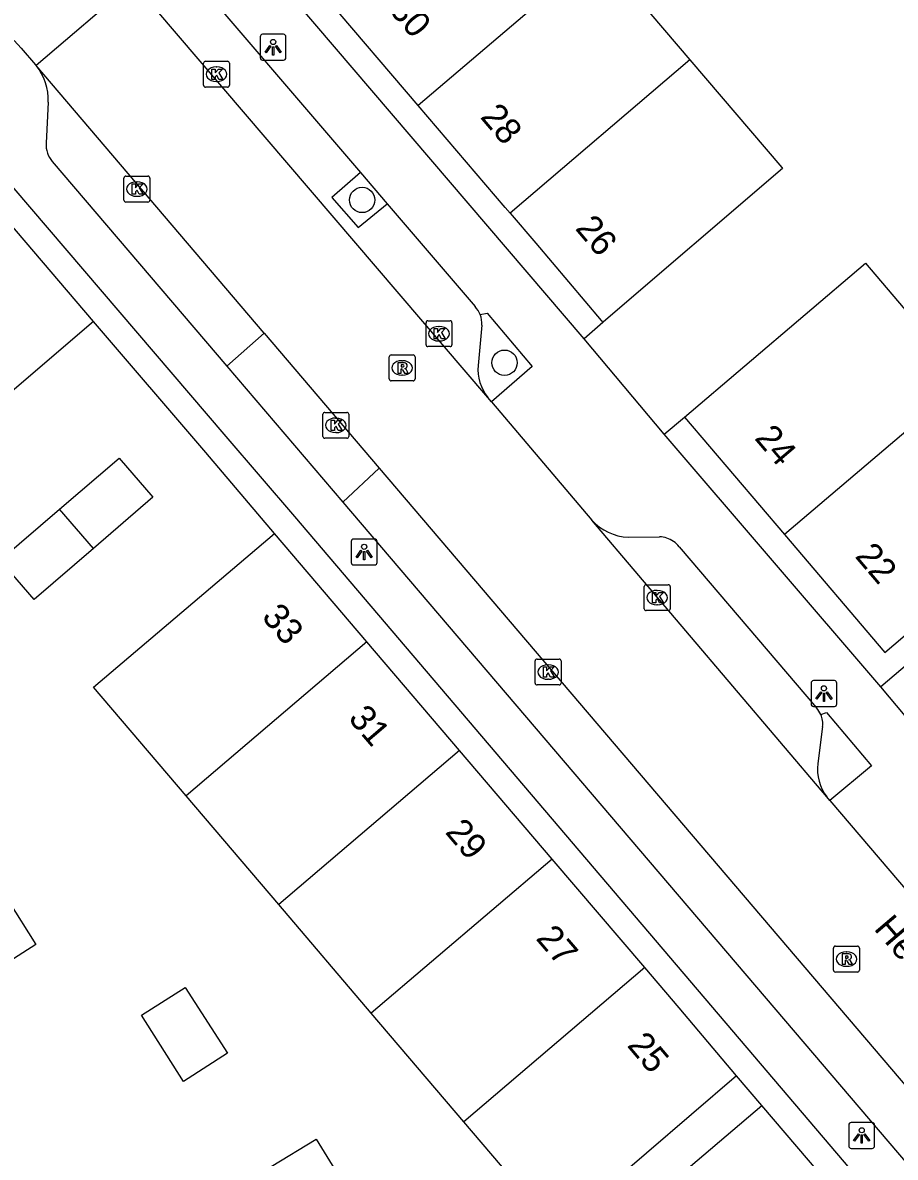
# Model space of a CAD drawing. Extents: x 160379 to 161131, y 383940 to 384849.
# Drawn here: x 160537.01 to 160570.71, y 384580.77 to 384624.58 of the extents above; entities that cross this region are included whole.
import ezdxf

# ---------------------------------------------------------------- set-up
doc = ezdxf.new("R2010")
doc.units = 0
for name, color, linetype in [('IMGEO_Boom', 7, 'Continuous'), ('IMGEO_Erf', 7, 'Continuous'), ('IMGEO_Groenvoorziening', 7, 'Continuous'), ('IMGEO_Kolk', 7, 'Continuous'), ('IMGEO_Lichtpunt', 7, 'Continuous'), ('IMGEO_Openbare_ruimte_label', 7, 'Continuous'), ('IMGEO_Pand', 7, 'Continuous'), ('IMGEO_Pand_nummerreeks', 7, 'Continuous'), ('IMGEO_Parkeervlak_open', 7, 'Continuous'), ('IMGEO_Rijbaan_lokaal_open', 7, 'Continuous'), ('IMGEO_Rioolput', 7, 'Continuous'), ('IMGEO_Voetpad_open', 7, 'Continuous')]:
    doc.layers.add(name, color=color, linetype=linetype)

msp = doc.modelspace()

# ---------------------------------------------------------------- linework, layer by layer
at = {"layer": 'IMGEO_Boom'}
for centre in [(160550.12, 384617.738), (160555.619, 384611.454)]:
    msp.add_circle(centre, 0.489, dxfattribs=at)
at = {"layer": 'IMGEO_Erf'}
for points in [[(160546.73, 384604.858), (160544.085, 384607.99), (160539.738, 384613.041)], [(160559.422, 384613.011), (160558.691, 384612.377)], [(160561.787, 384608.701), (160562.572, 384609.354)], [(160565.562, 384582.774), (160564.577, 384583.923)]]:
    msp.add_lwpolyline(points, dxfattribs=at)
at = {"layer": 'IMGEO_Groenvoorziening'}
msp.add_lwpolyline([(160578.569, 384607.304), (160579.15, 384606.609), (160578.387, 384605.942), (160570.15, 384598.933)], dxfattribs=at)
at = {"layer": 'IMGEO_Kolk'}
for p, q in [((160543.994, 384622.168), (160543.994, 384623.02)), ((160544.069, 384623.094), (160544.921, 384623.094)), ((160544.482, 384622.874), (160544.507, 384622.874)), ((160544.995, 384623.02), (160544.995, 384622.168)), ((160544.921, 384622.094), (160544.069, 384622.094)), ((160544.505, 384622.314), (160544.48, 384622.314)), ((160540.921, 384617.733), (160540.921, 384618.585)), ((160540.996, 384618.659), (160541.848, 384618.659)), ((160541.922, 384618.585), (160541.922, 384617.733)), ((160541.409, 384618.439), (160541.434, 384618.439)), ((160541.848, 384617.659), (160540.996, 384617.659)), ((160541.432, 384617.879), (160541.407, 384617.879)), ((160552.587, 384612.149), (160552.587, 384613.001)), ((160552.662, 384613.075), (160553.514, 384613.075)), ((160553.075, 384612.855), (160553.1, 384612.855)), ((160553.588, 384613.001), (160553.588, 384612.149)), ((160553.514, 384612.075), (160552.662, 384612.075)), ((160553.098, 384612.295), (160553.073, 384612.295)), ((160548.604, 384608.611), (160548.604, 384609.463)), ((160548.679, 384609.537), (160549.531, 384609.537)), ((160549.092, 384609.317), (160549.117, 384609.317)), ((160549.605, 384609.463), (160549.605, 384608.611)), ((160549.531, 384608.537), (160548.679, 384608.537)), ((160549.115, 384608.757), (160549.09, 384608.757)), ((160561.017, 384601.957), (160561.017, 384602.809)), ((160561.092, 384602.883), (160561.944, 384602.883)), ((160562.018, 384602.809), (160562.018, 384601.957)), ((160561.505, 384602.663), (160561.53, 384602.663)), ((160561.944, 384601.883), (160561.092, 384601.883)), ((160561.528, 384602.103), (160561.503, 384602.103)), ((160556.802, 384599.085), (160556.802, 384599.937)), ((160556.877, 384600.011), (160557.729, 384600.011)), ((160557.29, 384599.791), (160557.315, 384599.791)), ((160557.803, 384599.937), (160557.803, 384599.085)), ((160557.313, 384599.231), (160557.288, 384599.231)), ((160557.729, 384599.011), (160556.877, 384599.011))]:
    msp.add_line(p, q, dxfattribs=at)
for points in [[(160543.994, 384622.168), (160543.994, 384623.02)], [(160544.069, 384623.094), (160544.921, 384623.094)], [(160544.995, 384623.02), (160544.995, 384622.168)], [(160544.315, 384622.794), (160544.438, 384622.794), (160544.438, 384622.643), (160544.568, 384622.794), (160544.732, 384622.794), (160544.586, 384622.643), (160544.739, 384622.394), (160544.587, 384622.394), (160544.502, 384622.558), (160544.438, 384622.491), (160544.438, 384622.394), (160544.315, 384622.394), (160544.315, 384622.794)], [(160544.921, 384622.094), (160544.069, 384622.094)], [(160540.921, 384617.733), (160540.921, 384618.585)], [(160540.996, 384618.659), (160541.848, 384618.659)], [(160541.922, 384618.585), (160541.922, 384617.733)], [(160541.242, 384618.359), (160541.365, 384618.359), (160541.365, 384618.208), (160541.495, 384618.359), (160541.659, 384618.359), (160541.513, 384618.208), (160541.666, 384617.959), (160541.514, 384617.959), (160541.429, 384618.123), (160541.365, 384618.056), (160541.365, 384617.959), (160541.242, 384617.959), (160541.242, 384618.359)], [(160541.848, 384617.659), (160540.996, 384617.659)], [(160552.587, 384612.149), (160552.587, 384613.001)], [(160552.662, 384613.075), (160553.514, 384613.075)], [(160552.908, 384612.775), (160553.031, 384612.775), (160553.031, 384612.624), (160553.161, 384612.775), (160553.325, 384612.775), (160553.179, 384612.624), (160553.332, 384612.375), (160553.18, 384612.375), (160553.095, 384612.539), (160553.031, 384612.472), (160553.031, 384612.375), (160552.908, 384612.375), (160552.908, 384612.775)], [(160553.588, 384613.001), (160553.588, 384612.149)], [(160553.514, 384612.075), (160552.662, 384612.075)], [(160548.604, 384608.611), (160548.604, 384609.463)], [(160548.679, 384609.537), (160549.531, 384609.537)], [(160549.605, 384609.463), (160549.605, 384608.611)], [(160548.925, 384609.237), (160549.048, 384609.237), (160549.048, 384609.086), (160549.178, 384609.237), (160549.342, 384609.237), (160549.196, 384609.086), (160549.349, 384608.837), (160549.197, 384608.837), (160549.112, 384609.001), (160549.048, 384608.934), (160549.048, 384608.837), (160548.925, 384608.837), (160548.925, 384609.237)], [(160549.531, 384608.537), (160548.679, 384608.537)], [(160561.017, 384601.957), (160561.017, 384602.809)], [(160561.092, 384602.883), (160561.944, 384602.883)], [(160562.018, 384602.809), (160562.018, 384601.957)], [(160561.338, 384602.583), (160561.461, 384602.583), (160561.461, 384602.432), (160561.591, 384602.583), (160561.755, 384602.583), (160561.609, 384602.432), (160561.762, 384602.183), (160561.61, 384602.183), (160561.525, 384602.347), (160561.461, 384602.28), (160561.461, 384602.183), (160561.338, 384602.183), (160561.338, 384602.583)], [(160561.944, 384601.883), (160561.092, 384601.883)], [(160556.802, 384599.085), (160556.802, 384599.937)], [(160556.877, 384600.011), (160557.729, 384600.011)], [(160557.123, 384599.711), (160557.246, 384599.711), (160557.246, 384599.56), (160557.376, 384599.711), (160557.54, 384599.711), (160557.394, 384599.56), (160557.547, 384599.311), (160557.395, 384599.311), (160557.31, 384599.475), (160557.246, 384599.408), (160557.246, 384599.311), (160557.123, 384599.311), (160557.123, 384599.711)], [(160557.803, 384599.937), (160557.803, 384599.085)], [(160557.729, 384599.011), (160556.877, 384599.011)]]:
    msp.add_lwpolyline(points, dxfattribs=at)
for centre, start, end in [((160544.071, 384623.018), 91.552, 178.448), ((160544.071, 384623.018), 91.552, 178.448), ((160544.919, 384623.018), 1.552, 88.448), ((160544.919, 384623.018), 1.552, 88.448), ((160544.071, 384622.17), 181.552, 268.448), ((160544.071, 384622.17), 181.552, 268.448), ((160544.919, 384622.17), 271.552, 358.448), ((160544.919, 384622.17), 271.552, 358.448), ((160540.998, 384618.583), 91.552, 178.448), ((160540.998, 384618.583), 91.552, 178.448), ((160541.846, 384618.583), 1.552, 88.448), ((160541.846, 384618.583), 1.552, 88.448), ((160540.998, 384617.735), 181.552, 268.448), ((160540.998, 384617.735), 181.552, 268.448), ((160541.846, 384617.735), 271.552, 358.448), ((160541.846, 384617.735), 271.552, 358.448), ((160552.664, 384612.999), 91.552, 178.448), ((160552.664, 384612.999), 91.552, 178.448), ((160553.512, 384612.999), 1.552, 88.448), ((160553.512, 384612.999), 1.552, 88.448), ((160552.664, 384612.151), 181.552, 268.448), ((160552.664, 384612.151), 181.552, 268.448), ((160553.512, 384612.151), 271.552, 358.448), ((160553.512, 384612.151), 271.552, 358.448), ((160548.681, 384609.461), 91.552, 178.448), ((160548.681, 384609.461), 91.552, 178.448), ((160549.529, 384609.461), 1.552, 88.448), ((160549.529, 384609.461), 1.552, 88.448), ((160548.681, 384608.613), 181.552, 268.448), ((160548.681, 384608.613), 181.552, 268.448), ((160549.529, 384608.613), 271.552, 358.448), ((160549.529, 384608.613), 271.552, 358.448), ((160561.094, 384602.807), 91.552, 178.448), ((160561.094, 384602.807), 91.552, 178.448), ((160561.942, 384602.807), 1.552, 88.448), ((160561.942, 384602.807), 1.552, 88.448), ((160561.094, 384601.959), 181.552, 268.448), ((160561.094, 384601.959), 181.552, 268.448), ((160561.942, 384601.959), 271.552, 358.448), ((160561.942, 384601.959), 271.552, 358.448), ((160556.879, 384599.935), 91.552, 178.448), ((160556.879, 384599.935), 91.552, 178.448), ((160557.727, 384599.935), 1.552, 88.448), ((160557.727, 384599.935), 1.552, 88.448), ((160556.879, 384599.087), 181.552, 268.448), ((160556.879, 384599.087), 181.552, 268.448), ((160557.727, 384599.087), 271.552, 358.448), ((160557.727, 384599.087), 271.552, 358.448)]:
    msp.add_arc(centre, 0.0765, start, end, dxfattribs=at)
for centre, major_axis, ratio, start_param, end_param in [((160544.481, 384622.594), (-0.387, 0.002), 0.722429, 4.712389, 7.853982), ((160544.506, 384622.594), (-0.39, 0.002), 0.717154, 1.570796, 4.712389), ((160541.408, 384618.159), (-0.387, 0.002), 0.722429, 4.712389, 7.853982), ((160541.433, 384618.159), (-0.39, 0.002), 0.717154, 1.570796, 4.712389), ((160553.074, 384612.575), (-0.387, 0.002), 0.722429, 4.712389, 7.853982), ((160553.099, 384612.575), (-0.39, 0.002), 0.717154, 1.570796, 4.712389), ((160549.091, 384609.037), (-0.387, 0.002), 0.722429, 4.712389, 7.853982), ((160549.116, 384609.037), (-0.39, 0.002), 0.717154, 1.570796, 4.712389), ((160561.504, 384602.383), (-0.387, 0.002), 0.722429, 4.712389, 7.853982), ((160561.529, 384602.383), (-0.39, 0.002), 0.717154, 1.570796, 4.712389), ((160557.289, 384599.511), (-0.387, 0.002), 0.722429, 4.712389, 7.853982), ((160557.314, 384599.511), (-0.39, 0.002), 0.717154, 1.570796, 4.712389)]:
    msp.add_ellipse(centre, major_axis=major_axis, ratio=ratio, start_param=start_param, end_param=end_param, dxfattribs=at)
at = {"layer": 'IMGEO_Lichtpunt'}
for p, q in [((160546.182, 384624.041), (160546.182, 384623.234)), ((160546.182, 384624.041), (160546.182, 384623.234)), ((160547.084, 384624.136), (160546.276, 384624.136)), ((160547.084, 384624.136), (160546.276, 384624.136)), ((160547.178, 384623.234), (160547.178, 384624.041)), ((160547.178, 384623.234), (160547.178, 384624.041)), ((160546.276, 384623.14), (160547.084, 384623.14)), ((160546.276, 384623.14), (160547.084, 384623.14)), ((160549.701, 384604.548), (160549.701, 384603.741)), ((160549.701, 384604.548), (160549.701, 384603.741)), ((160550.603, 384604.643), (160549.795, 384604.643)), ((160550.603, 384604.643), (160549.795, 384604.643)), ((160550.697, 384603.741), (160550.697, 384604.548)), ((160550.697, 384603.741), (160550.697, 384604.548)), ((160549.795, 384603.647), (160550.603, 384603.647)), ((160549.795, 384603.647), (160550.603, 384603.647)), ((160567.458, 384599.083), (160567.458, 384598.276)), ((160567.458, 384599.083), (160567.458, 384598.276)), ((160568.36, 384599.178), (160567.552, 384599.178)), ((160568.36, 384599.178), (160567.552, 384599.178)), ((160568.454, 384598.276), (160568.454, 384599.083)), ((160568.454, 384598.276), (160568.454, 384599.083)), ((160567.552, 384598.182), (160568.36, 384598.182)), ((160567.552, 384598.182), (160568.36, 384598.182)), ((160569.818, 384582.115), (160569.01, 384582.115)), ((160569.818, 384582.115), (160569.01, 384582.115)), ((160568.916, 384582.02), (160568.916, 384581.213)), ((160568.916, 384582.02), (160568.916, 384581.213)), ((160569.912, 384581.213), (160569.912, 384582.02)), ((160569.912, 384581.213), (160569.912, 384582.02)), ((160569.01, 384581.119), (160569.818, 384581.119)), ((160569.01, 384581.119), (160569.818, 384581.119))]:
    msp.add_line(p, q, dxfattribs=at)
for points in [[(160546.556, 384623.705), (160546.595, 384623.677), (160546.407, 384623.415), (160546.369, 384623.442), (160546.556, 384623.705)], [(160546.658, 384623.657), (160546.705, 384623.657), (160546.705, 384623.335), (160546.658, 384623.335), (160546.658, 384623.657)], [(160546.768, 384623.677), (160546.806, 384623.704), (160546.993, 384623.442), (160546.954, 384623.414), (160546.768, 384623.677)], [(160550.075, 384604.212), (160550.114, 384604.184), (160549.926, 384603.922), (160549.888, 384603.949), (160550.075, 384604.212)], [(160550.177, 384604.164), (160550.224, 384604.164), (160550.224, 384603.842), (160550.177, 384603.842), (160550.177, 384604.164)], [(160550.287, 384604.184), (160550.325, 384604.211), (160550.512, 384603.949), (160550.473, 384603.921), (160550.287, 384604.184)], [(160567.832, 384598.747), (160567.871, 384598.719), (160567.683, 384598.457), (160567.645, 384598.484), (160567.832, 384598.747)], [(160567.934, 384598.699), (160567.981, 384598.699), (160567.981, 384598.377), (160567.934, 384598.377), (160567.934, 384598.699)], [(160568.044, 384598.719), (160568.082, 384598.746), (160568.269, 384598.484), (160568.23, 384598.456), (160568.044, 384598.719)], [(160569.29, 384581.684), (160569.329, 384581.656), (160569.141, 384581.394), (160569.103, 384581.421), (160569.29, 384581.684)], [(160569.502, 384581.656), (160569.54, 384581.683), (160569.727, 384581.421), (160569.688, 384581.393), (160569.502, 384581.656)], [(160569.392, 384581.636), (160569.439, 384581.636), (160569.439, 384581.314), (160569.392, 384581.314), (160569.392, 384581.636)]]:
    msp.add_lwpolyline(points, dxfattribs=at)
for centre in [(160546.681, 384623.839), (160550.2, 384604.346), (160567.957, 384598.881), (160569.415, 384581.818)]:
    msp.add_circle(centre, 0.0994, dxfattribs=at)
for centre, start, end in [((160546.276, 384624.041), 90, 180), ((160546.276, 384624.041), 90, 180), ((160547.084, 384624.041), 0, 90), ((160547.084, 384624.041), 0, 90), ((160546.276, 384623.234), 180, 270), ((160546.276, 384623.234), 180, 270), ((160547.084, 384623.234), 270, 0), ((160547.084, 384623.234), 270, 360), ((160549.795, 384604.548), 90, 180), ((160549.795, 384604.548), 90, 180), ((160550.603, 384604.548), 0, 90), ((160550.603, 384604.548), 0, 90), ((160549.795, 384603.741), 180, 270), ((160549.795, 384603.741), 180, 270), ((160550.603, 384603.741), 270, 0), ((160550.603, 384603.741), 270, 360), ((160567.552, 384599.083), 90, 180), ((160567.552, 384599.083), 90, 180), ((160568.36, 384599.083), 0, 90), ((160568.36, 384599.083), 0, 90), ((160567.552, 384598.276), 180, 270), ((160567.552, 384598.276), 180, 270), ((160568.36, 384598.276), 270, 0), ((160568.36, 384598.276), 270, 360), ((160569.01, 384582.02), 90, 180), ((160569.01, 384582.02), 90, 180), ((160569.818, 384582.02), 0, 90), ((160569.818, 384582.02), 0, 90), ((160569.01, 384581.213), 180, 270), ((160569.01, 384581.213), 180, 270), ((160569.818, 384581.213), 270, 0), ((160569.818, 384581.213), 270, 360)]:
    msp.add_arc(centre, 0.0946, start, end, dxfattribs=at)
at = {"layer": 'IMGEO_Pand'}
for points in [[(160559.235, 384627.312), (160552.287, 384621.39)], [(160559.235, 384627.312), (160562.78, 384623.153)], [(160552.287, 384621.39), (160548.74, 384625.548)], [(160562.78, 384623.153), (160555.833, 384617.232)], [(160562.78, 384623.153), (160566.325, 384618.994), (160566.361, 384618.952), (160559.441, 384613.028), (160559.422, 384613.011)], [(160555.833, 384617.232), (160555.646, 384617.452), (160552.287, 384621.39)], [(160539.738, 384613.041), (160533.783, 384620.017)], [(160555.833, 384617.232), (160556.83, 384616.065), (160559.348, 384613.089), (160559.422, 384613.011)], [(160562.572, 384609.354), (160569.566, 384615.295), (160573.423, 384610.752)], [(160539.738, 384613.041), (160535.503, 384609.431)], [(160573.423, 384610.752), (160566.433, 384604.818)], [(160562.572, 384609.354), (160566.433, 384604.818)], [(160538.436, 384605.799), (160540.733, 384607.767), (160542.03, 384606.257), (160539.742, 384604.284)], [(160566.433, 384604.818), (160570.304, 384600.269), (160577.28, 384606.208)], [(160539.742, 384604.284), (160537.453, 384602.311), (160536.142, 384603.834), (160538.436, 384605.799)], [(160539.742, 384604.284), (160538.436, 384605.799)], [(160543.323, 384594.733), (160539.748, 384598.93), (160546.73, 384604.858)], [(160550.299, 384600.676), (160546.73, 384604.858)], [(160550.299, 384600.676), (160543.323, 384594.733)], [(160553.878, 384596.483), (160550.299, 384600.676)], [(160553.878, 384596.483), (160546.898, 384590.537)], [(160557.457, 384592.29), (160553.878, 384596.483)], [(160546.898, 384590.537), (160543.323, 384594.733)], [(160557.457, 384592.29), (160550.474, 384586.34)], [(160561.037, 384588.097), (160557.457, 384592.29)], [(160536.449, 384590.691), (160537.523, 384588.986), (160534.957, 384587.36), (160533.879, 384589.09)], [(160550.474, 384586.34), (160546.898, 384590.537)], [(160561.037, 384588.097), (160554.049, 384582.144)], [(160564.577, 384583.923), (160562.366, 384586.539), (160561.037, 384588.097)], [(160543.221, 384583.698), (160541.6, 384586.256), (160543.281, 384587.327), (160544.923, 384584.793), (160543.221, 384583.698)], [(160554.049, 384582.144), (160550.474, 384586.34)], [(160564.577, 384583.923), (160557.624, 384577.947), (160554.049, 384582.144)], [(160562.099, 384572.702), (160558.581, 384576.839), (160565.562, 384582.774)], [(160569.083, 384578.641), (160565.562, 384582.774)], [(160548.178, 384577.833), (160546.602, 384580.42), (160548.339, 384581.476), (160549.922, 384578.896)]]:
    msp.add_lwpolyline(points, dxfattribs=at)
at = {"layer": 'IMGEO_Parkeervlak_open'}
for points in [[(160550.055, 384618.797), (160548.944, 384617.832), (160549.965, 384616.678), (160551.084, 384617.595)], [(160554.738, 384612.901), (160554.596, 384611.349)], [(160567.905, 384597.403), (160567.721, 384595.973)]]:
    msp.add_lwpolyline(points, dxfattribs=at)
for centre, radius, start, end in [((160553.822, 384612.979), 0.919, 355.1119, 21.2264), ((160556.448, 384611.235), 1.856, 176.4667, 217.2963), ((160567.028, 384597.51), 0.884, 353.0213, 23.8595), ((160569.453, 384595.75), 1.746, 172.6643, 217.415)]:
    msp.add_arc(centre, radius, start, end, dxfattribs=at)
at = {"layer": 'IMGEO_Rijbaan_lokaal_open'}
for points in [[(160541.279, 384626.131), (160537.53, 384622.931)], [(160554.972, 384610.11), (160541.279, 384626.131)], [(160536.678, 384623.897), (160536.951, 384623.599), (160537.508, 384622.957), (160537.53, 384622.931)], [(160546.34, 384612.597), (160537.53, 384622.931)], [(160544.893, 384611.316), (160546.34, 384612.597)], [(160546.34, 384612.597), (160550.781, 384607.389)], [(160544.893, 384611.316), (160549.373, 384606.064)], [(160555.111, 384609.947), (160554.972, 384610.11)], [(160555.111, 384609.947), (160558.988, 384605.381)], [(160550.781, 384607.389), (160549.373, 384606.064)], [(160550.781, 384607.389), (160594.077, 384556.607)], [(160568.066, 384594.689), (160558.988, 384605.381)], [(160568.182, 384594.551), (160568.066, 384594.689)], [(160568.182, 384594.551), (160575.352, 384586.144)]]:
    msp.add_lwpolyline(points, dxfattribs=at)
at = {"layer": 'IMGEO_Rioolput'}
for p, q in [((160551.165, 384610.827), (160551.165, 384611.679)), ((160551.24, 384611.753), (160552.092, 384611.753)), ((160551.653, 384611.533), (160551.678, 384611.533)), ((160552.166, 384611.679), (160552.166, 384610.827)), ((160552.092, 384610.753), (160551.24, 384610.753)), ((160551.676, 384610.973), (160551.651, 384610.973)), ((160568.323, 384588.001), (160568.323, 384588.853)), ((160568.398, 384588.927), (160569.25, 384588.927)), ((160568.811, 384588.707), (160568.836, 384588.707)), ((160569.324, 384588.853), (160569.324, 384588.001)), ((160569.25, 384587.927), (160568.398, 384587.927)), ((160568.834, 384588.147), (160568.809, 384588.147))]:
    msp.add_line(p, q, dxfattribs=at)
for points in [[(160551.165, 384610.827), (160551.165, 384611.679)], [(160551.24, 384611.753), (160552.092, 384611.753)], [(160551.754, 384611.451), (160551.502, 384611.453), (160551.502, 384611.053)], [(160552.166, 384611.679), (160552.166, 384610.827)], [(160551.502, 384611.053), (160551.626, 384611.053), (160551.626, 384611.215), (160551.637, 384611.215)], [(160551.68, 384611.372), (160551.626, 384611.372), (160551.626, 384611.291)], [(160551.626, 384611.291), (160551.678, 384611.291)], [(160551.684, 384611.186), (160551.755, 384611.053), (160551.895, 384611.053), (160551.83, 384611.179)], [(160552.092, 384610.753), (160551.24, 384610.753)], [(160568.323, 384588.001), (160568.323, 384588.853)], [(160568.398, 384588.927), (160569.25, 384588.927)], [(160569.324, 384588.853), (160569.324, 384588.001)], [(160568.912, 384588.625), (160568.66, 384588.627), (160568.66, 384588.227)], [(160568.66, 384588.227), (160568.784, 384588.227), (160568.784, 384588.389), (160568.795, 384588.389)], [(160568.838, 384588.546), (160568.784, 384588.546), (160568.784, 384588.465)], [(160568.784, 384588.465), (160568.836, 384588.465)], [(160568.842, 384588.36), (160568.913, 384588.227), (160569.053, 384588.227), (160568.988, 384588.353)], [(160569.25, 384587.927), (160568.398, 384587.927)]]:
    msp.add_lwpolyline(points, dxfattribs=at)
for centre, radius, start, end in [((160551.242, 384611.677), 0.0765, 91.552, 178.448), ((160551.242, 384611.677), 0.0765, 91.552, 178.448), ((160552.09, 384611.677), 0.0765, 1.552, 88.448), ((160552.09, 384611.677), 0.0765, 1.552, 88.448), ((160551.636, 384611.162), 0.0533, 26.0293, 88.6989), ((160551.662, 384611.48), 0.19, 274.7715, 282.9687), ((160551.686, 384611.276), 0.0964, 77.0061, 93.1865), ((160551.7, 384611.333), 0.0378, 276.6634, 79.6772), ((160551.753, 384611.341), 0.109, 350.3612, 89.416), ((160551.751, 384611.341), 0.112, 277.5842, 350.9817), ((160551.735, 384611.126), 0.108, 29.5134, 73.7905), ((160551.242, 384610.829), 0.0765, 181.552, 268.448), ((160551.242, 384610.829), 0.0765, 181.552, 268.448), ((160552.09, 384610.829), 0.0765, 271.552, 358.448), ((160552.09, 384610.829), 0.0765, 271.552, 358.448), ((160568.4, 384588.851), 0.0765, 91.552, 178.448), ((160568.4, 384588.851), 0.0765, 91.552, 178.448), ((160569.248, 384588.851), 0.0765, 1.552, 88.448), ((160569.248, 384588.851), 0.0765, 1.552, 88.448), ((160568.794, 384588.336), 0.0533, 26.0293, 88.6989), ((160568.82, 384588.654), 0.19, 274.7715, 282.9687), ((160568.844, 384588.45), 0.0964, 77.0061, 93.1865), ((160568.858, 384588.507), 0.0378, 276.6634, 79.6772), ((160568.911, 384588.515), 0.109, 350.3612, 89.416), ((160568.909, 384588.515), 0.112, 277.5842, 350.9817), ((160568.893, 384588.3), 0.108, 29.5134, 73.7905), ((160568.4, 384588.003), 0.0765, 181.552, 268.448), ((160568.4, 384588.003), 0.0765, 181.552, 268.448), ((160569.248, 384588.003), 0.0765, 271.552, 358.448), ((160569.248, 384588.003), 0.0765, 271.552, 358.448)]:
    msp.add_arc(centre, radius, start, end, dxfattribs=at)
for centre, major_axis, ratio, start_param, end_param in [((160551.652, 384611.253), (-0.387, 0.002), 0.722429, 4.712389, 7.853982), ((160551.677, 384611.253), (-0.39, 0.002), 0.717154, 1.570796, 4.712389), ((160568.81, 384588.427), (-0.387, 0.002), 0.722429, 4.712389, 7.853982), ((160568.835, 384588.427), (-0.39, 0.002), 0.717154, 1.570796, 4.712389)]:
    msp.add_ellipse(centre, major_axis=major_axis, ratio=ratio, start_param=start_param, end_param=end_param, dxfattribs=at)
at = {"layer": 'IMGEO_Voetpad_open'}
for points in [[(160558.691, 384612.377), (160544.574, 384628.905), (160499.831, 384681.477), (160499.817, 384698.107), (160517.199, 384711.18), (160531.839, 384722.221)], [(160540.854, 384629.561), (160542.733, 384627.355), (160550.055, 384618.797)], [(160537.997, 384621.515), (160537.91, 384619.929)], [(160601.299, 384499.323), (160600.989, 384502.935), (160599.078, 384522.405), (160597.158, 384544.586), (160596.904, 384547.52), (160547.519, 384605.522), (160544.872, 384608.601), (160534.548, 384620.664)], [(160538.151, 384619.219), (160544.893, 384611.316)], [(160550.055, 384618.797), (160551.084, 384617.595)], [(160551.084, 384617.595), (160554.483, 384613.622)], [(160554.679, 384613.312), (160554.943, 384613.37), (160556.687, 384611.309), (160555.111, 384609.947)], [(160561.787, 384608.701), (160558.691, 384612.377)], [(160570.15, 384598.933), (160561.787, 384608.701)], [(160549.373, 384606.064), (160595.282, 384552.25)], [(160560.4, 384604.717), (160561.61, 384604.737)], [(160562.364, 384604.35), (160567.665, 384598.124)], [(160571.697, 384597.097), (160570.15, 384598.933)], [(160567.836, 384597.868), (160568.06, 384597.946), (160569.797, 384595.89), (160568.182, 384594.551)]]:
    msp.add_lwpolyline(points, dxfattribs=at)
for centre, radius, start, end in [((160535.797, 384621.574), 2.201, 358.4517, 38.0536), ((160538.937, 384619.882), 1.028, 177.3589, 220.1393), ((160553.8, 384612.973), 0.942, 21.0776, 43.5293), ((160560.485, 384606.732), 2.017, 222.0539, 267.5751), ((160561.61, 384603.98), 0.757, 68.6343, 90.0261), ((160561.57, 384603.726), 1.01, 38.1774, 71.7742), ((160567.024, 384597.511), 0.887, 23.7534, 43.7299)]:
    msp.add_arc(centre, radius, start, end, dxfattribs=at)

# ---------------------------------------------------------------- texts
at = {"layer": 'IMGEO_Openbare_ruimte_label'}
msp.add_text('Heemskerkstraat', height=1, rotation=310.3776, dxfattribs=at).set_placement((160569.854, 384589.59))
at = {"layer": 'IMGEO_Pand_nummerreeks'}
for s, rotation, p in [('30', 310.4621, (160551.132, 384625.056)), ('28', 310.4621, (160554.651, 384620.931)), ('26', 310.2329, (160558.319, 384616.627)), ('24', 310.399, (160565.247, 384608.526)), ('22', 310.399, (160569.125, 384603.969)), ('33', 310.4793, (160546.207, 384601.62)), ('31', 310.4793, (160549.552, 384597.701)), ('29', 310.4793, (160553.296, 384593.315)), ('27', 310.4793, (160556.8, 384589.21)), ('25', 310.2042, (160560.324, 384585.082))]:
    msp.add_text(s, height=1, rotation=rotation, dxfattribs=at).set_placement(p)

doc.saveas('drawing.dxf')
